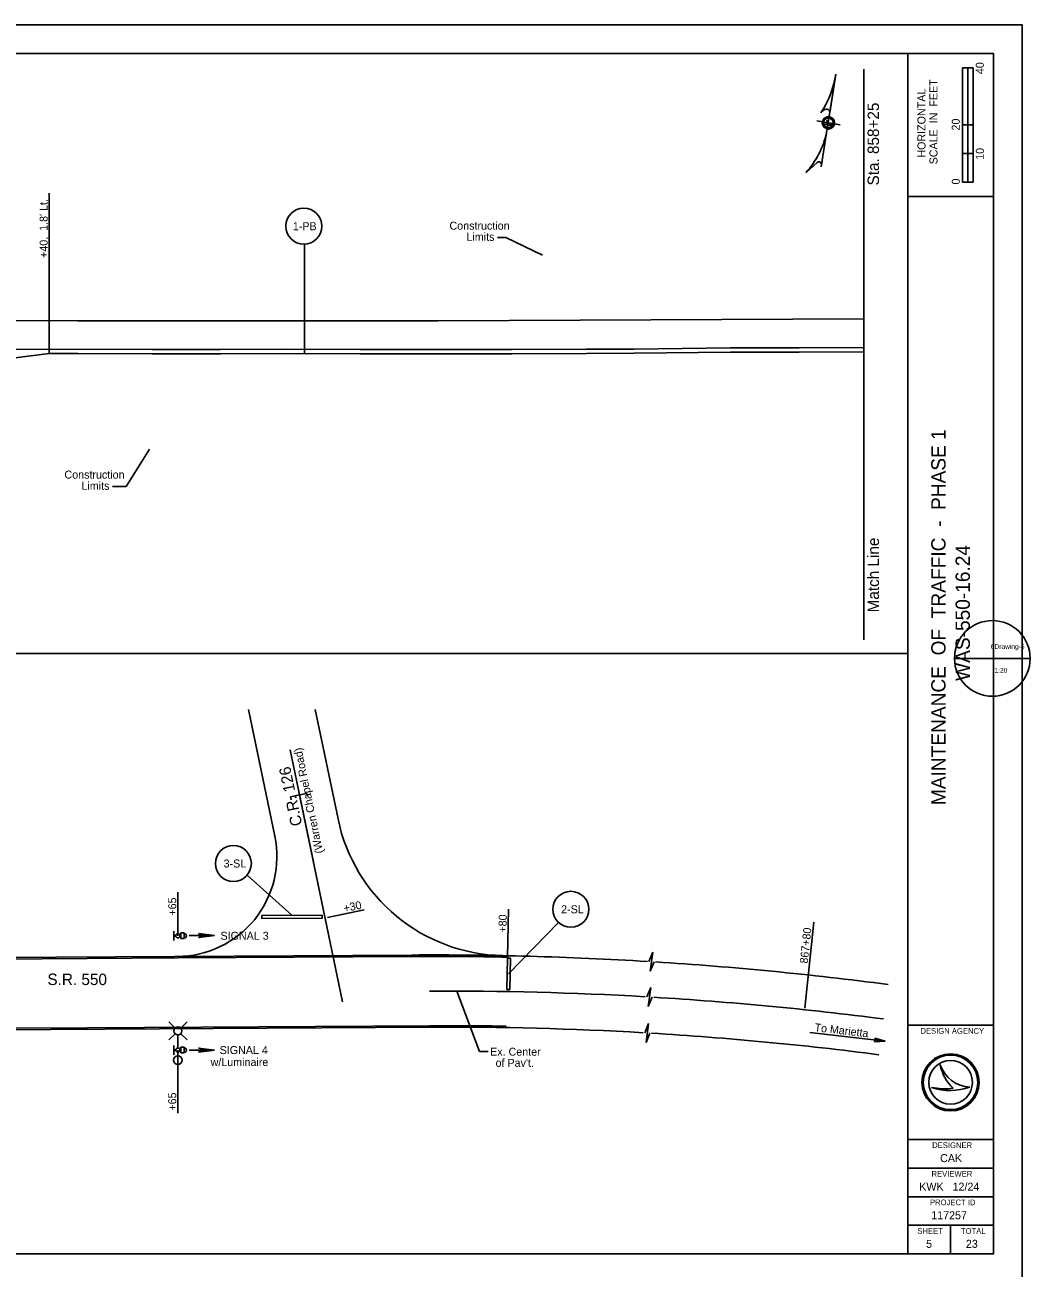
# Model space of a CAD drawing. Extents: x -1395 to 1843, y -1176 to 1887.
# Drawn here: x 331.2 to 682.8, y 5 to 440 of the extents above; entities that cross this region are included whole.
import ezdxf

# ---------------------------------------------------------------- set-up
doc = ezdxf.new("R2010")
doc.units = 0
for name, color, linetype in [('Default', 7, 'Continuous'), ('DR_P_Headwall', 7, 'Continuous'), ('DR_X_Ditch', 7, 'Continuous'), ('PV_X_COP', 7, 'Continuous'), ('PV_X_EOP', 7, 'Continuous'), ('SH_Border', 7, 'Continuous'), ('SH_Cut_Line', 7, 'Continuous'), ('SH_Major_Grid_Line', 7, 'Continuous'), ('SH_Named_Boundary', 7, 'Continuous'), ('SH_Text', 7, 'Continuous'), ('XS_P_Headwall', 7, 'Continuous'), ('XS_P_Pavt_Surface', 7, 'Continuous')]:
    doc.layers.add(name, color=color, linetype=linetype)

msp = doc.modelspace()

# ---------------------------------------------------------------- linework, layer by layer
at = {"layer": 'Default'}
for p, q in [((628.34, 84.2), (632.08, 84.38)), ((628.34, 84.2), (628.34, 84.2)), ((632.08, 84.38), (628.47, 85.43)), ((628.47, 85.43), (628.47, 85.43))]:
    msp.add_line(p, q, dxfattribs=at)
for centre, radius, start, end in [((479.68, -1085.67), 1187.6, 86.69653, 90.33829), ((479.68, -1085.67), 1187.6, 82.65249, 86.54884), ((627.47, 84.92), 1.12, 320.4114, 27.0922)]:
    msp.add_arc(centre, radius, start, end, dxfattribs=at)
at = {"layer": 'DR_P_Headwall'}
for points in [[(435.21, 128.5), (435.21, 127.5), (414.02, 127.37), (414.01, 128.37)], [(500.8, 102.49), (499.8, 102.51), (500.03, 113.51), (501.03, 113.49)]]:
    msp.add_lwpolyline(points, close=True, dxfattribs=at)
at = {"layer": 'DR_X_Ditch'}
for p, q in [((409.39, 200.48), (418.6, 156.16)), ((432.77, 200.48), (440.71, 162.16)), ((233.82, 113.07), (466.57, 114.56)), ((233.34, 87.89), (472.74, 89.31))]:
    msp.add_line(p, q, dxfattribs=at)
for centre, radius, start, end in [((499.46, 174.34), 60, 191.7125, 268.8811), ((384.34, 149.03), 35, 270.365, 11.7448), ((474.37, -1110.42), 1225, 86.50792, 90.36504), ((474.37, -1110.42), 1225, 82.55425, 86.37542), ((479.68, -1085.67), 1175, 86.69047, 90.33829), ((479.68, -1085.67), 1175, 82.65249, 86.55218)]:
    msp.add_arc(centre, radius, start, end, dxfattribs=at)
at = {"layer": 'PV_X_COP'}
for p, q in [((280.28, 336.58), (349.71, 336.46)), ((349.71, 336.46), (475.76, 336.4)), ((475.76, 336.4), (624.71, 337.09)), ((169.71, 112.07), (384.56, 113.53)), ((384.56, 113.53), (466.57, 114.06)), ((326.05, 88.94), (353.04, 89.1)), ((353.04, 89.1), (472.74, 89.81)), ((353.04, 89.1), (472.74, 89.81))]:
    msp.add_line(p, q, dxfattribs=at)
msp.add_lwpolyline([(297.94, 326.5), (375.75, 326.44), (399.61, 326.37), (422.43, 326.54), (448.47, 326.36), (475.76, 326.4), (501.52, 326.38), (527.66, 326.48), (544.16, 326.59), (577.99, 326.95), (602.05, 326.98), (624.69, 327.09)], dxfattribs=at)
for centre, radius, start, end in [((474.37, -1110.42), 1224.5, 88.79875, 90.36504), ((479.68, -1085.67), 1175.5, 89.03216, 90.33829)]:
    msp.add_arc(centre, radius, start, end, dxfattribs=at)
at = {"layer": 'PV_X_EOP'}
for p, q in [((656.37, 218.34), (682.83, 218.34)), ((669.72, 218.34), (681.05, 218.34))]:
    msp.add_line(p, q, dxfattribs=at)
msp.add_circle((669.6, 218.34), 13.23, dxfattribs=at)
at = {"layer": 'SH_Border'}
msp.add_lwpolyline([(0, 0), (680, 0), (680, 440), (0, 440)], close=True, dxfattribs=at)
at = {"layer": 'SH_Cut_Line'}
for p, q in [((640, 10), (640, 430)), ((640, 380), (670, 380)), ((640, 90), (670, 90)), ((640, 50), (670, 50)), ((640, 40), (670, 40)), ((640, 30), (670, 30)), ((640, 20), (670, 20))]:
    msp.add_line(p, q, dxfattribs=at)
msp.add_lwpolyline([(30, 430), (670, 430), (670, 10), (30, 10)], close=True, dxfattribs=at)
at = {"layer": 'SH_Major_Grid_Line'}
msp.add_line((288.03, 220), (640, 220), dxfattribs=at)
for centre in [(428.75, 369.55), (404.1, 146.57), (522.14, 130.55)]:
    msp.add_circle(centre, 6.29, dxfattribs=at)
at = {"layer": 'SH_Named_Boundary'}
for p, q in [((614.9, 422.75), (611.65, 402.23)), ((614.9, 422.75), (612.73, 409.23)), ((659.13, 385), (659.13, 425)), ((662.88, 425), (659.13, 425)), ((659.13, 405), (659.13, 425)), ((659.13, 425), (661, 425)), ((661, 425), (661.02, 425)), ((661.02, 425), (661.02, 405)), ((662.88, 425), (662.88, 385)), ((610.82, 410.25), (609.66, 409.24)), ((612.73, 409.23), (612.73, 409.23)), ((608.2, 406.43), (616.35, 405.07)), ((661.02, 405), (659.13, 405)), ((662.87, 405), (661, 405)), ((661, 405), (661, 395)), ((662.87, 395), (662.87, 405)), ((609.75, 390.29), (611.65, 402.23)), ((604.46, 388.4), (608.32, 391.83)), ((661, 395), (659.13, 395)), ((659.13, 395), (659.13, 385)), ((661, 385), (661, 395)), ((661, 395), (662.87, 395)), ((604.45, 388.41), (604.46, 388.4)), ((604.46, 388.4), (604.46, 388.4)), ((662.88, 385), (659.13, 385)), ((659.13, 385), (661, 385)), ((424.01, 186.31), (432.13, 147.14)), ((442.28, 98.18), (427.05, 171.62)), ((500.39, 130.56), (500.04, 113.81)), ((607.16, 126.09), (604, 96.01)), ((549.5, 112.25), (550.85, 115.5)), ((550.85, 115.5), (549.94, 108.94)), ((549.94, 108.94), (551.29, 112.18)), ((548.78, 99.9), (550.13, 103.15)), ((550.13, 103.15), (549.21, 96.58)), ((549.21, 96.58), (550.56, 99.83)), ((548.03, 87.32), (549.38, 90.57)), ((549.38, 90.57), (548.47, 84)), ((548.47, 84), (549.82, 87.25)), ((605.75, 87.49), (632.08, 84.38)), ((651.35, 76.19), (651.35, 76.19)), ((655, 70), (655, 70)), ((648.34, 68.19), (648.34, 68.19)), ((661.75, 68.37), (661.75, 68.37)), ((655, 10), (655, 20)), ((647.5, 13.5), (647.5, 13.5))]:
    msp.add_line(p, q, dxfattribs=at)
for centre, radius in [((612.27, 405.72), 2.17), ((612.27, 405.72), 1.7), ((655, 70), 10), ((655, 70), 9.54), ((655, 70), 9.54), ((655, 70), 7.64)]:
    msp.add_circle(centre, radius, dxfattribs=at)
for centre, radius, start, end in [((578.17, 429.22), 37.3, 327.6016, 350.0038), ((611.58, 409.37), 1.16, 352.6305, 131.7143), ((611.86, 409.33), 4.12, 255.8713, 276.4809), ((612.77, 409.5), 4.58, 245.372, 281.9173), ((614.2, 407.59), 2.61, 200.2874, 259.2391), ((624.12, 410.83), 13.05, 198.5288, 205.362), ((581.03, 409.36), 31.43, 318.1774, 346.8959), ((608.94, 391.13), 0.936, 350.9817, 131.6305), ((662.32, 79.95), 11.6, 198.9257, 198.9319), ((666.93, 79.4), 15.91, 191.6379, 191.6421), ((662.32, 79.95), 11.6, 198.9319, 267.1657), ((666.93, 79.4), 15.91, 191.6421, 226.0947), ((654.79, 87.4), 20.26, 251.4576, 290.0832), ((652.96, 93.09), 25.32, 259.4964, 259.4995), ((654.79, 87.4), 20.26, 251.4527, 251.4576), ((652.96, 93.09), 25.32, 259.4995, 276.6672)]:
    msp.add_arc(centre, radius, start, end, dxfattribs=at)
at = {"layer": 'SH_Text'}
for p, q in [((383.31, 119.65), (383.3, 122.94)), ((385.73, 120.29), (385.72, 122.31)), ((386.88, 122.31), (385.72, 122.31)), ((386.87, 120.29), (386.87, 122.31)), ((387.36, 122.01), (386.88, 122)), ((391.92, 122.06), (397.55, 121.35)), ((383.3, 121.4), (383.96, 121.4)), ((383.3, 121.2), (383.96, 121.2)), ((385.46, 121.4), (385.73, 121.4)), ((385.46, 121.2), (385.73, 121.2)), ((386.87, 120.29), (385.73, 120.29)), ((387.36, 120.56), (386.88, 120.56)), ((388.6, 121.35), (397.55, 121.35)), ((397.55, 121.35), (391.92, 120.65)), ((383.72, 88.99), (381.54, 91.18)), ((383.72, 87.02), (381.54, 84.83)), ((385.7, 88.99), (387.89, 91.18)), ((385.7, 87.02), (387.89, 84.83)), ((383.3, 79.65), (383.3, 82.94)), ((384.71, 82.06), (384.71, 86.61)), ((383.3, 81.4), (383.96, 81.4)), ((383.3, 81.2), (383.96, 81.2)), ((384.71, 79.29), (384.71, 80.54)), ((385.46, 81.4), (385.73, 81.4)), ((385.46, 81.2), (385.73, 81.2)), ((385.73, 80.29), (385.73, 82.31)), ((386.88, 82.31), (385.73, 82.31)), ((386.87, 80.29), (385.73, 80.29)), ((386.87, 80.29), (386.87, 82.31)), ((387.36, 82), (386.88, 82)), ((387.36, 80.56), (386.88, 80.56)), ((388.61, 81.3), (397.55, 81.3)), ((391.93, 82), (397.55, 81.3)), ((397.55, 81.3), (391.93, 80.6))]:
    msp.add_line(p, q, dxfattribs=at)
for centre, radius in [((384.71, 121.3), 0.757), ((384.71, 88.01), 1.4), ((384.71, 77.79), 1.5), ((384.71, 81.3), 0.757)]:
    msp.add_circle(centre, radius, dxfattribs=at)
for centre, radius in [((391.92, 121.35), 0.702), ((391.93, 81.3), 0.703)]:
    msp.add_arc(centre, radius, 270, 90, dxfattribs=at)
for centre, major_axis in [((387.36, 121.28), (0.001, -0.721)), ((387.36, 81.28), (0, -0.721))]:
    msp.add_ellipse(centre, major_axis=major_axis, ratio=0.45371, start_param=0, end_param=3.141593, dxfattribs=at)
at = {"layer": 'XS_P_Headwall'}
msp.add_line((339.71, 324.96), (304, 320.46), dxfattribs=at)
msp.add_lwpolyline([(339.71, 324.96), (349.71, 324.96), (375.74, 324.94), (399.61, 324.87), (422.43, 325.04), (448.47, 324.86), (475.76, 324.9), (501.52, 324.88), (527.67, 324.98), (544.18, 325.09), (578, 325.45), (602.06, 325.48), (624.7, 325.59)], dxfattribs=at)
at = {"layer": 'XS_P_Pavt_Surface'}
for p, q in [((624.71, 424.55), (624.71, 323.18)), ((339.71, 324.96), (339.71, 381.17)), ((496.56, 365.58), (499.4, 365.58)), ((512.21, 359.44), (499.4, 365.58)), ((428.97, 324.95), (428.97, 363.26)), ((624.71, 323.18), (624.71, 224.85)), ((374.71, 291.53), (366.59, 278.48)), ((361.87, 278.48), (366.59, 278.48)), ((424.14, 169.93), (427.27, 170.58)), ((424.14, 169.93), (424.37, 168.82)), ((427.27, 170.58), (429.82, 171.1)), ((427.27, 170.58), (427.5, 169.47)), ((429.82, 171.1), (430.05, 170)), ((408.89, 142.48), (424.61, 128.44)), ((384.71, 136.49), (384.71, 121.3)), ((449.86, 130.34), (437.03, 127.68)), ((517.86, 125.94), (500.34, 108)), ((490.17, 80.85), (482.27, 101.92)), ((384.71, 81.3), (384.71, 59.24)), ((490.17, 80.85), (493.19, 80.85))]:
    msp.add_line(p, q, dxfattribs=at)

# ---------------------------------------------------------------- texts
at = {"layer": 'DR_X_Ditch'}
for s, p in [('Sta. 858+25', (629.96, 383.8)), ('Match Line', (629.96, 234.43))]:
    msp.add_text(s, height=4, rotation=90, dxfattribs=at).set_placement(p)
at = {"layer": 'PV_X_EOP'}
for s, height, p in [('6', 1.67, (669.01, 221.67)), ('Drawing-5', 1.667, (670.37, 221.67)), ('1:20', 1.667, (670.37, 213.34))]:
    msp.add_text(s, height=height, dxfattribs=at).set_placement(p)
at = {"layer": 'SH_Named_Boundary'}
for s, height, rotation, p in [('40', 2.8, 90, (666.62, 422.77)), ('SCALE  IN  FEET', 2.8, 90, (650.42, 391.2)), ('HORIZONTAL', 2.8, 90, (646.22, 393.54)), ('20', 2.8, 90, (658.21, 403.04)), ('10', 2.8, 90, (666.62, 392.77)), ('0', 2.8, 90, (658.21, 384.15)), ("+40,  1.8' Lt.", 2.8, 90.0561, (339.14, 358.46)), ('1-PB', 2.8, 0.0561, (424.9, 368.14)), ('Construction', 2.8, 359.9439, (479.71, 368.35)), ('Limits', 2.8, 359.9439, (485.65, 364.45)), ('MAINTENANCE  OF  TRAFFIC  -  PHASE 1', 5, 90, (653.25, 167)), ('Construction', 2.8, 359.9439, (345.01, 281.25)), ('Limits', 2.8, 359.9439, (350.96, 277.34)), ('WAS-550-16.24', 5, 90, (661.75, 210.46)), ('3-SL', 2.8, 0.0561, (400.7, 145.17)), ('+65', 2.8, 90.0561, (384.12, 128.34)), ('+30', 2.8, 11.7685, (442.94, 129.51)), ('2-SL', 2.8, 0.0561, (518.75, 129.15)), ('+80', 2.8, 88.8548, (499.63, 122.38)), ('SIGNAL 3', 2.8, 0.0561, (399.6, 119.89)), ('867+80', 2.8, 84.0503, (605.03, 111.46)), ('S.R. 550', 4, 359.9439, (339.06, 104.06)), ('To Marietta', 2.8, 353.3262, (607.3, 87.92)), ('SIGNAL 4', 2.8, 0.0871, (399.3, 79.89)), ('w/Luminaire', 2.8, 0.0871, (396.14, 75.68)), ('Ex. Center', 2.8, 359.9439, (493.92, 79.33)), ("of Pav't.", 2.8, 359.9439, (495.83, 75.43)), ('+65', 2.8, 90.0561, (384.12, 60.11))]:
    msp.add_text(s, height=height, rotation=rotation, dxfattribs=at).set_placement(p)
for s, height, p in [('DESIGN AGENCY', 2, (644.45, 87)), ('DESIGNER', 2, (648.57, 47)), ('CAK', 2.8, (651.33, 42.1)), ('KWK   12/24', 2.8, (644.04, 32.1)), ('REVIEWER', 2, (648.33, 37)), ('PROJECT ID', 2, (647.8, 27)), ('117257', 2.8, (648.23, 22.1)), ('SHEET', 2, (643.39, 17)), ('TOTAL', 2, (658.63, 17)), ('5', 2.8, (646.43, 12.1)), ('23', 2.8, (660.35, 12.1))]:
    msp.add_text(s, height=height, dxfattribs=at).set_placement(p)
at = {"layer": 'XS_P_Headwall'}
for s, height, p in [('(Warren Chapel Road)', 2.8, (435.54, 150.38)), ('C.R. 126', 4, (428.22, 160.09))]:
    msp.add_text(s, height=height, rotation=101.7125, dxfattribs=at).set_placement(p)

doc.saveas('drawing.dxf')
